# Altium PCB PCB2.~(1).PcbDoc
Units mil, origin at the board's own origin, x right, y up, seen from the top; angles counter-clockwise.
Board outline 6000 x 4000 mil, 2 copper layers (Top Layer, Bottom Layer); 36 components, 20 nets, 89 pads, 0 vias.
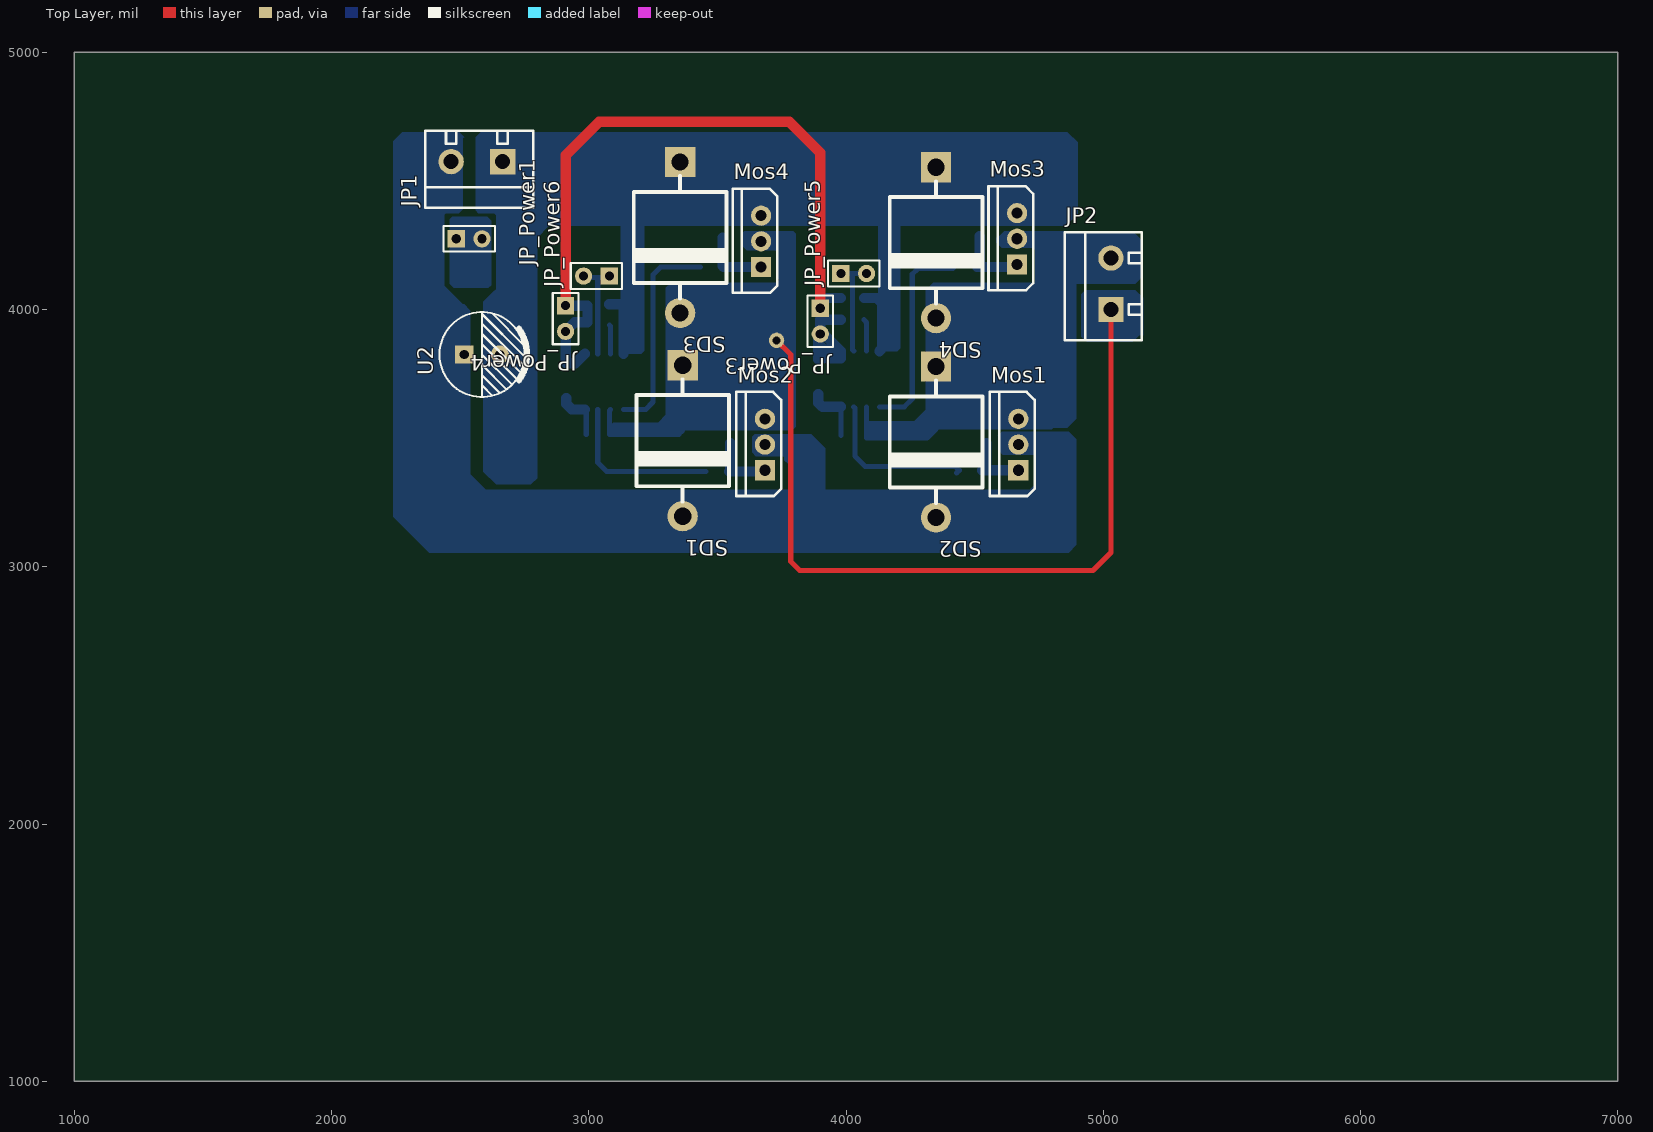
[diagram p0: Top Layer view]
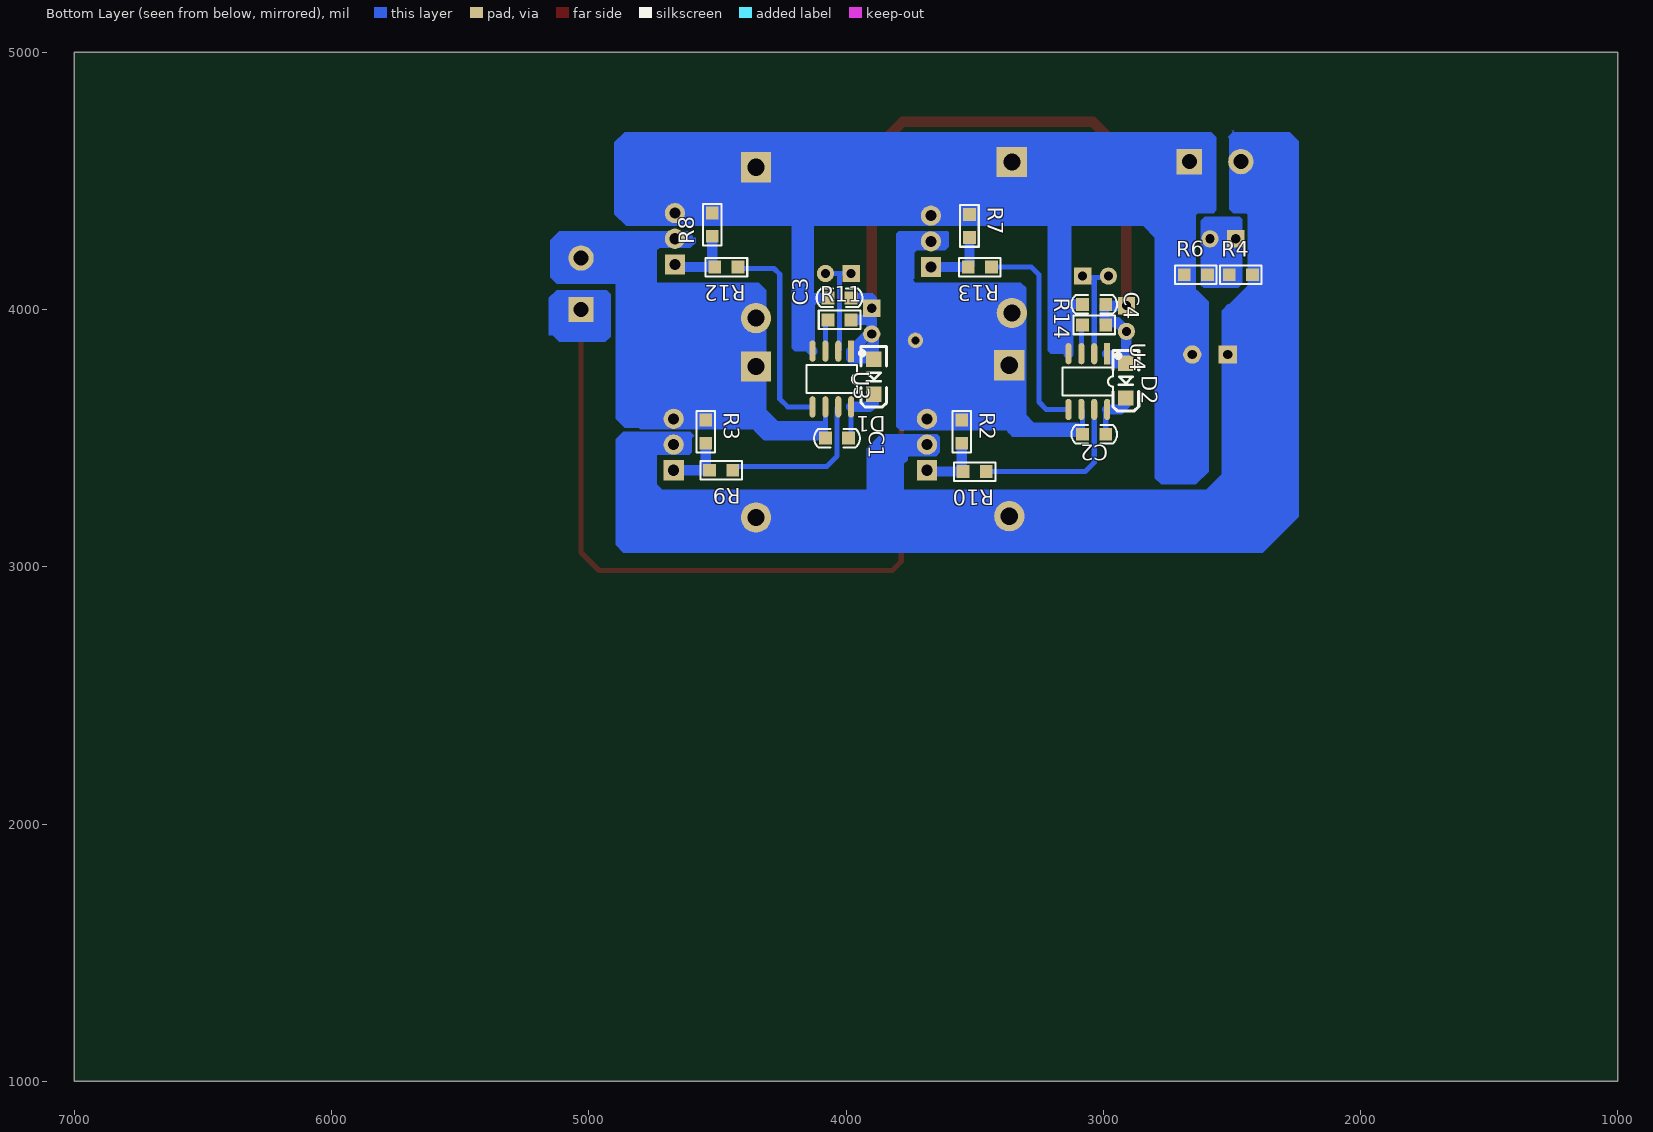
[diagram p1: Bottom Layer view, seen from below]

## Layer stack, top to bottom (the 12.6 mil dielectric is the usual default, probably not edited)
Top Solder: solder mask 0.4, Solder Resist, Dk 3.5
Top Layer: signal copper 1.4
Dielectric 1: dielectric 12.6, FR-4, Dk 4.8
Bottom Layer: signal copper 1.4
Bottom Solder: solder mask 0.4, Solder Resist, Dk 3.5

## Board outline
1000,1000 7000,1000 7000,5000 1000,5000

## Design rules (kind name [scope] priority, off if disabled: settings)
Clearance [All] p1: gap=10
PolygonConnect [All] p1: connectstyle=Relief reliefconductorwidth=10 reliefentries=4 polygonreliefangle="90 Angle" airgapwidth=10
RoutingVias [All] p1: holewidth=28 width=50 viastyle="Through Hole" minholewidth=28 minwidth=50 maxholewidth=28 maxwidth=50
SolderMaskExpansion [All] p1: expansion=4
UnpouredPolygon [All] p1: allowunpoured=FALSE
Width [All] p1: maxlimit=60 minlimit=20 preferedwidth=20
29 further rules are at their usual default settings.

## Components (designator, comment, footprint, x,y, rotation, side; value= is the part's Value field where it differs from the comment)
C1 "Cap" "C 0805" 4035,3500 r180 bottom
C2 "Cap" "C 0805" 3035,3515 r180 bottom
C3 "Cap" "C 0805" 4025,4045 r0 bottom
C4 "Cap" "C 0805" 3035,4020 r0 bottom
D1 "4148" D1206 3895,3735 r270 bottom
D2 "4148" D1206 2915,3720 r270 bottom
JP1 "HDR-1X2" KF301-2P 2665,4575 r180 top
JP2 "HDR-1X2" KF301-2P 5030,4000 r90 top
JP_Power1 "CON2" HDR-1x2 2485,4275 r0 top
JP_Power3 "CON2" HDR-1x2 3900,4005 r270 top
JP_Power4 "CON2" HDR-1x2 2910,4015 r270 top
JP_Power5 "CON2" HDR-1x2 3980,4140 r0 top
JP_Power6 "CON2" HDR-1x2 3080,4130 r180 top
Mos1 "IRF540" TO220A 4670,3475 r90 top
Mos2 "IRF540" TO220A 3685,3475 r90 top
Mos3 "IRF540" TO220A 4665,4275 r90 top
Mos4 "IRF540" TO220A 3670,4265 r90 top
R2 "Res1" "R 0805" 3550,3525 r270 bottom
R3 "Res1" "R 0805" 4545,3525 r270 bottom
R4 "RES" "R 0805" 2465,4135 r180 bottom
R6 "RES" "R 0805" 2640,4135 r180 bottom
R7 "Res1" "R 0805" 3520,4325 r270 bottom
R8 "Res1" "R 0805" 4520,4330 r90 bottom
R9 "Res1" "R 0805" 4485,3375 r0 bottom
R10 "Res1" "R 0805" 3500,3370 r0 bottom
R11 "Res1" "R 0805" 4025,3960 r180 bottom
R12 "Res1" "R 0805" 4465,4165 r0 bottom
R13 "Res1" "R 0805" 3480,4165 r0 bottom
R14 "Res1" "R 0805" 3035,3940 r180 bottom
SD1 "FR607" R-6 3365,3490 r270 top
SD2 "FR607" R-6 4350,3485 r270 top
SD3 "FR607" R-6 3355,4280 r270 top
SD4 "FR607" R-6 4350,4260 r270 top
U2 "470uf" "CAP 3.5*8*11.5" 2585,3825 r0 top
U3 "IR2104" SOP8_M 4055,3730 r270 bottom
U4 "IR2104" SOP8_M 3060,3720 r270 bottom

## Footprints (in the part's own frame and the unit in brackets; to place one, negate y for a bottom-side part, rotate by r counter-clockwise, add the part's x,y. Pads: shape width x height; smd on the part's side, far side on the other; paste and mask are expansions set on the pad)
"C 0805" [mil] "无极性贴片电容"
  rect 50x50 smd: 1(-45,0) 2(45,0)
  silkscreen extent -89,-36 89,36, body extent -39,-24 39,24, height 20
"CAP 3.5*8*11.5" [mm] "脚距3.5mm直径8mm高度11.5mm"
  rect 1.8x1.8 hole 0.9: 1(-1.75,0)
  round 1.8 hole 0.9: 2(1.75,0)
  silkscreen extent -4.2,-4.2 4.5,4.2, body extent -4,-4 4.01,4, height 11.53
D1206 [mil] "1/4W"
  rect 60x60 smd: 1(-71,3) 2(64,3)
  silkscreen extent -121,-47 114,53, body extent -73,-27 65,33, height 59
HDR-1x2 [mm] "排针，2脚"
  rect 1.7x1.7 hole 0.9: 1(0,0)
  round 1.7 hole 0.9: 2(2.54,0)
  silkscreen extent -1.27,-1.27 3.81,1.27, body extent -1.27,-1.27 3.81,1.27, height 8.5
KF301-2P [mm] "可拼接端子/6A"
  rect 2.5x2.5 hole 1.5: 1(0,0)
  round 2.5 hole 1.5: 2(5.08,0)
  silkscreen extent -3.05,-3.05 7.62,4.57, body extent -2.87,-3 7.63,4.6, height 10.05
"R 0805" [mil] "1/8W贴片电阻"
  rect 50x50 smd: 1(-45,0) 2(45,0)
  silkscreen extent -81,-36 81,36, body extent -39,-25 39,25, height 20
R-6 [mm] "8.8*14.9mm(直径，脚距）"
  rect 3x3 hole 1.7: 1(-7.45,0)
  round 3 hole 1.7: 2(7.45,0)
  silkscreen extent -6.06,-4.57 6.02,4.57, body extent -8.1,-4.4 8.1,4.4, height 8.85
SOP8_M [mm] "5*6*1.8mm（长宽高）"
  rect 2.1x0.6 smd: 1(-2.75,1.905)
  oval 2.1x0.6 smd: 2(-2.75,0.635) 3(-2.75,-0.635) 4(-2.75,-1.905) 5(2.75,-1.905) 6(2.75,-0.635) 7(2.75,0.635) 8(2.75,1.905)
  silkscreen extent -2.69,-2.5 1.4,3.15, body extent -3,-2.5 3,2.5, height 1.9
TO220A [mm] "220，3脚晶体管"
  rect 2x2 hole 1.1: 1(-2.54,0)
  round 2 hole 1.1: 2(0,0) 3(2.54,0)
  silkscreen extent -5.08,-1.6 5.21,2.82, body extent -5.15,-1.53 5.15,2.9, height 18.5

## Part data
C1 C2 C3 C4: "Capacitor"
D1 D2: library part Diode, "Default Diode"
JP1 JP2: library part "Header 2", "2P接插件"
JP_Power1 JP_Power3 JP_Power4 JP_Power5 JP_Power6: "Connector"
Mos1 Mos2 Mos3 Mos4: library part NMOS
R2 R3 R7 R8 R9 R10 R11 R12 R13 R14: "Resistor"
SD1 SD2 SD3 SD4: library part 1N5822
U2: library part CAP, "Capacitor"

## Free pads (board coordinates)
  round 60 hole 30: 0(3730,3880)

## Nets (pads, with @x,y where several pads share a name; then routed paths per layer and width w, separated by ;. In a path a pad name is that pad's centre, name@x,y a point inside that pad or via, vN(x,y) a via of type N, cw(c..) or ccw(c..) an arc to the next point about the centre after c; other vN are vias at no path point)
+12V: C3.1 C4.1 D1.1 D2.1 JP_Power3.1 JP_Power3.2 JP_Power4.1 JP_Power4.2 R11.2 R14.2 U3.1 U4.1 | length 3405.6
  Top Layer w40: JP_Power4.1 2910,4600 3040,4730 3780,4730 3900,4610 JP_Power3.1
  Bottom Layer w40: JP_Power4.1 2995,4015 2995,3950 2945,3950 JP_Power4.2 2910,3793 D2.1 2947.73,3791 U4.1 ; 3900,3860 3915,3845 3970,3845 3980,3835 3980,3810 3896,3810 D1.1 3892,3883.73 3913.27,3905 U3.1 ; JP_Power3.2 3900,3960 R11.2 ; JP_Power3.1 3900,4040 3905,4045 C3.1
+60V: JP1.2 Mos1.2 Mos2.2 R4.2 SD1.2 SD2.2 U2.1 | length 4573.8
  Bottom Layer w40: 2420,3860 2455,3825 U2.1 ; JP1.2 2420,4530 R4.2 2420,3245 2473.31,3191.69 SD2.2 4731.69,3191.69 4770,3230 4770,3450 4745,3475 Mos1.2 ; Mos2.2 3795,3475 3810,3460 3810,3195
GND: C3.2 C4.2 JP1.1 Mos3.3 Mos4.3 R6.1 R7.1 R8.2 SD3.1 SD4.1 U2.2 U3.4 U4.4 | length 5164.3
  Bottom Layer w40: U2.2 2685,3825 R6.1 2685,4555 JP1.1 3120,4575 ; C4.2 3125,4020 3143.46,4001.54 3143.46,4551.54 3120,4575 ; U4.4 3135,4010 ; R7.1 3665,4370 Mos4.3 3685,4380 3685,4516.61 3628.31,4573.31 ; C3.2 4120,4045 4140,4025 ; U3.4 4140,3848.27 4140,4025 ; R8.2 Mos3.3 4665,4515 4606.69,4573.31 4095,4573.31 ; 3120,4575 3353.31,4575 SD3.1 3628.31,4573.31 ; 3628.31,4573.31 4095,4573.31 ; 4095,4573.31 4143.46,4524.84 4143.46,4028.46 4140,4025
NetC1_2: C1.2 D1.2 U3.8 | length 239.5
  Bottom Layer w20: C1.2@3980,3510 U3.8
  Bottom Layer w40: D1.2 3892,3638 3908.27,3621.73 U3.8
NetC2_2: C2.2 D2.2 U4.8 | length 203.6
  Bottom Layer w20: U4.8 2990,3606.73 C2.2
  Bottom Layer w40: D2.2 2912,3633 2933.27,3611.73 U4.8
NetJP_Power1_1: JP_Power1.1 JP_Power1.2 R4.1 R6.2 | length 227.1
  Bottom Layer w40: R4.1@2500,4135 R4.1 R6.2 2595,4260 JP_Power1.2@2590,4265
NetJP_Power5_1: JP_Power5.1 JP_Power5.2 U3.2 | length 403.8
  Bottom Layer w20: JP_Power5.1 4025,4140 ; U3.2 4025,3843.27 4025,4140 ; JP_Power5.2 4025,4140
NetJP_Power6_1: JP_Power6.1 JP_Power6.2 U4.2 | length 396.7
  Bottom Layer w20: JP_Power6.2@3000,4125 3035,4125 ; U4.2 3035,4125 ; JP_Power6.1@3100,4125 3035,4125
NetR9_1: R9.1 U3.7 | length 635.7
  Bottom Layer w20: U3.7 4035,3616.73 4035,3430 4075,3390 4425,3390 R9.1 R9.1@4430,3365
NetR10_1: R10.1 U4.7 | length 641.2
  Bottom Layer w20: U4.7 3035,3405 3070,3370 R10.1
NetR11_1: R11.1 U3.3 | length 125.9
  Bottom Layer w20: R11.1 4080,3950 U3.3
NetR12_1: R12.1 U3.5 | length 799.1
  Bottom Layer w20: U3.5 4226.73,3621.73 4257.5,3652.5 4257.5,4137.5 4280,4160 4415,4160 R12.1
NetR13_1: R13.1 U4.5 | length 819.1
  Bottom Layer w20: U4.5 3221.73,3611.73 3250,3640 3250,4135 3280,4165 R13.1
NetR14_1: R14.1 U4.3 | length 113.8
  Bottom Layer w20: R14.1 3085,3935 U4.3
S1H: Mos2.1 R2.2 R10.2 | length 254.1
  Bottom Layer w40: R2.2 3550,3375 R10.2 3680,3370 Mos2.1
S1L: Mos4.1 R7.2 R13.2 | length 262.1
  Bottom Layer w40: R7.2 3520,4170 R13.2 Mos4.1
S2H: Mos1.1 R3.2 R9.2 | length 251.2
  Bottom Layer w20: R9.2 R9.2@4545,3390
  Bottom Layer w40: R9.2 Mos1.1 ; R9.2@4545,3390 R3.2
S2L: Mos3.1 R8.1 R12.2 | length 271.2
  Bottom Layer w40: R12.2 4655,4165 Mos3.1 ; R8.1 4520,4180 R12.2@4525,4175
VS1: C2.1 JP2.1 Mos2.3 Mos4.2 pad.0 R2.1 SD1.1 SD3.2 U4.6 | length 5331.1
  Top Layer w20: pad.0 3785,3825 3785,3020 3820,2985 4960,2985 5030,3055 JP2.1
  Bottom Layer w20: U4.6 3080,3606.73 C2.1 3350,3515 3365,3530 SD1.1 ; SD3.2 3365,3976.69 SD1.1 ; R2.1 3680,3570 Mos2.3 3730,3575 3765,3610 3765,3783.31 ; Mos4.2 3735,4265 3765,4235 3765,3783.31 ; SD1.1 3765,3783.31
VS2: C1.1 JP2.2 Mos1.3 Mos3.2 R3.1 SD2.1 SD4.2 U3.6 | length 2253.5
  Bottom Layer w20: U3.6 C1.1 4315,3500 4350,3535 SD2.1 ; SD4.2 SD2.1 ; R3.1 4550,3575 Mos1.3 4740,3575 4760,3595 4760,3805 ; Mos3.2 4750,4275 4760,4265 4760,3805 ; SD2.1 4728.31,3778.31 4755,3805 4760,3805

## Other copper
Bottom Layer:
  region net VS1: 5115,3875 5140,3900 5155,3900 5155,4045 5125,4075 5100,4075 5090,4065 5090,4020
  region net VS1: 5125,4075 4930,4075 4915,4060 4915,3895 4935,3875 5115,3875
  region net VS2: 4860,4305 5115,4305 5150,4270 5150,4125 5125,4100 4840,4100
  region net GND: 4130,3838.27 4198.27,3838.27 4210,3850 4210,4380 4175,4415 4115,4415 4115,4378.46 4143.46,4350
  region net GND: 3135,3828.27 3203.27,3828.27 3215,3840 3215,3850 3215,4390 3173.46,4390 3143.46,4420 3135,4411.54
  region net VS2: 4595,4280 4595,4285 4615,4305 4810,4305 4845,4270 4850,4270 4850,4235 4845,4240 4675,4240
  region net VS2: 4615,4305 4625,4295 4815,4295 4815,4300 4855,4260 4875,4260 4875,3610 4800,3535 4350,3535 4315,3500 4080,3500 4080,3565 4265,3565 4310,3610 4310,4075 4340,4105 4735,4105 4735,4230 4725,4240 4605,4240 4585,4260 4585,4280 4595,4280 4620,4305
  region net VS2: 4810,4305 4860,4305 4895,4270 4895,3575 4860,3540 4780,3540 4715,3605 4715,3950 4735,3970
  region net GND: 4725,4690 4860,4690 4900,4650 4900,4370 4855,4325 4725,4325 4725,4380 4615,4490 4640,4515 4640,4670
  region net VS1: 3790,3530 3805,3545 3805,3555 3330,3555 3325,3560 3295,3530
  region net VS1: 3795,4305 3805,4295 3805,3555 3795,3545 3380,3545 3350,3515 3080,3515 3080,3545 3095,3560 3270,3560 3300,3590 3300,4085 3320,4105 3730,4105 3740,4115 3735,4120 3735,4220 3725,4230 3615,4230 3600,4245 3600,4300 3605,4305
  region net +60V: 3865,3515 3920,3460 3920,3290 3900,3290 3865,3255 3840,3280 3775,3280 3775,3400 3760,3415 3760,3425 3755,3430 3650,3430 3635,3445 3635,3505 3645,3515
  region net +60V: 2890,3300 4715,3300 4740,3325 4795,3270 4795,3235 4685,3125 4650,3160 2835,3160 2835,3270 2860,3295
  region net +60V: 2815,3055 4865,3055 4895,3085 4895,3495 4865,3525 4605,3525 4590,3510 4600,3500 4600,3445 4610,3435 4620,3435 4735,3435 4735,3270 4745,3260 4725,3240 2940,3240 2890,3290
  region net GND: 2560,4445 2560,4385 2570,4375 2635,4375 2635,4405 2605,4435 2605,4445 2575,4445 2570,4450
  region net +60V: 2510,4440 2510,4390 2495,4375 2435,4375 2435,4410 2445,4420 2445,4445 2455,4445 2490,4480
  region net +60V: 2500,4695 2495,4690 2275,4690 2240,4655 2240,3195 2380,3055 2815,3055 2905,3145 2905,3285 2890,3300 2870,3300 2600,3300 2540,3360 2540,3995 2535,4000 2515,4020 2510,4020 2420,4110 2420,4350 2510,4440 2510,4665 2515,4670 2490,4695
  region net GND: 2640,4175 2640,4380 2665,4405 2730,4340 2730,4135 2705,4110 2700,4115 2665,4115
  region net GND: 2615,4055 2655,4095 2665,4085 2665,4030 2635,4030 2625,4020 2615,4030 2610,4030
  region net GND: 2875,4325 2845,4325 2800,4280 2800,3345 2775,3320 2640,3320 2590,3370 2590,4030 2615,4055 2640,4055 2640,4175 2665,4200 2665,4350 2655,4350 2560,4445 2560,4670 2580,4690 2605,4690
  region net GND: 2605,4690 4725,4690 4775,4640 4775,4365 4735,4325 2875,4325 2560,4640 2605,4685
  region net NetJP_Power1_1: 2605,4360 2620,4345 2620,4095 2610,4085 2475,4085 2460,4100 2460,4350 2470,4360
